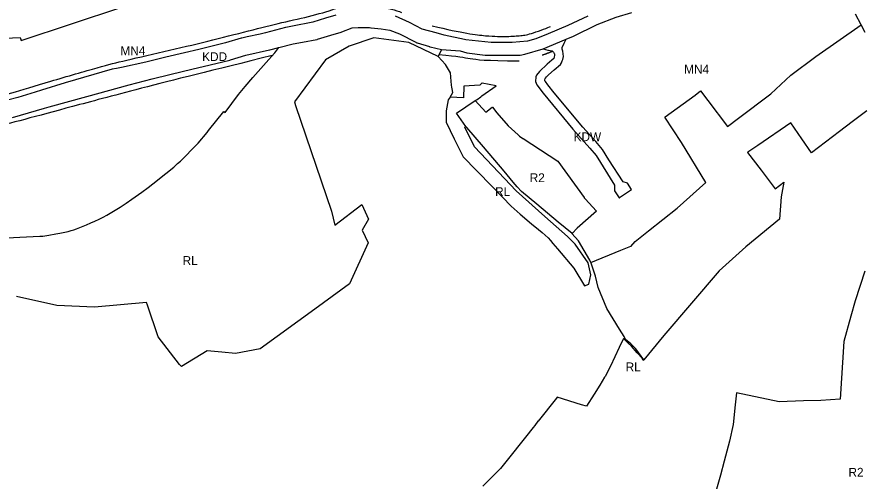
# Model space of a CAD drawing. Extents: x 7413438 to 7416393, y 5541665 to 5544118.
# Drawn here: x 7414051 to 7414626, y 5542093 to 5542408 of the extents above; entities that cross this region are included whole.
import ezdxf

# ---------------------------------------------------------------- set-up
doc = ezdxf.new("R2010")
doc.units = 0
for name, color, linetype in [('linie_rozgraniczajace', 7, 'Continuous'), ('linie_zabudowy_nieprzekraczalne', 7, 'Continuous'), ('oznaczenia_przeznaczen', 7, 'Continuous')]:
    doc.layers.add(name, color=color, linetype=linetype)

msp = doc.modelspace()

# ---------------------------------------------------------------- linework, layer by layer
at = {"layer": 'linie_rozgraniczajace'}
for p, q in [((7414054.25, 5542392.12), (7414122.55, 5542414.66)), ((7414458.25, 5542407.86), (7414468.88, 5542411.04)), ((7414260.97, 5542407.08), (7414252.35, 5542404.42)), ((7414261, 5542407.09), (7414260.97, 5542407.08)), ((7414267.9, 5542409.18), (7414261, 5542407.09)), ((7414317.89, 5542404.33), (7414308.55, 5542408.59)), ((7414438.96, 5542408.53), (7414425.48, 5542402.16)), ((7414445.44, 5542402.83), (7414458.25, 5542407.86)), ((7414624.64, 5542402.58), (7414620.71, 5542409.88)), ((7414233.79, 5542400.73), (7414220.22, 5542397.26)), ((7414233.97, 5542400.78), (7414233.78, 5542400.9)), ((7414233.78, 5542400.9), (7414233.79, 5542400.73)), ((7414238.46, 5542401.79), (7414233.97, 5542400.78)), ((7414252.35, 5542404.42), (7414238.46, 5542401.79)), ((7414271.96, 5542397.89), (7414279.06, 5542400.58)), ((7414279.06, 5542400.58), (7414283.2, 5542400.95)), ((7414283.2, 5542400.95), (7414290.85, 5542400.77)), ((7414290.85, 5542400.77), (7414291.73, 5542400.67)), ((7414291.73, 5542400.67), (7414291.88, 5542400.65)), ((7414291.88, 5542400.65), (7414292.03, 5542400.64)), ((7414292.03, 5542400.64), (7414298.76, 5542399.86)), ((7414298.76, 5542399.86), (7414298.76, 5542399.86)), ((7414298.76, 5542399.86), (7414304.5, 5542399.11)), ((7414304.5, 5542399.11), (7414311.09, 5542396.59)), ((7414326.66, 5542399.81), (7414317.89, 5542404.33)), ((7414336.03, 5542397.24), (7414326.66, 5542399.81)), ((7414425.48, 5542402.16), (7414412.19, 5542396.53)), ((7414429.21, 5542395.06), (7414445.44, 5542402.83)), ((7414593.86, 5542381.07), (7414624.64, 5542402.58)), ((7414627.37, 5542397.55), (7414624.64, 5542402.58)), ((7414012.45, 5542392.63), (7414053.52, 5542393.94)), ((7414053.52, 5542393.94), (7414054.25, 5542392.12)), ((7414203.61, 5542393.52), (7414193.03, 5542390.35)), ((7414203.92, 5542393.61), (7414203.61, 5542393.52)), ((7414204.02, 5542393.63), (7414203.92, 5542393.61)), ((7414207.72, 5542394.46), (7414204.02, 5542393.63)), ((7414216.45, 5542396.42), (7414207.72, 5542394.46)), ((7414220.22, 5542397.26), (7414216.45, 5542396.42)), ((7414255.57, 5542392.85), (7414264.49, 5542395.61)), ((7414264.49, 5542395.61), (7414271.58, 5542397.75)), ((7414271.58, 5542397.75), (7414271.62, 5542397.77)), ((7414271.62, 5542397.77), (7414271.96, 5542397.89)), ((7414293.72, 5542393.72), (7414276.97, 5542388.1)), ((7414317.51, 5542390.69), (7414293.72, 5542393.72)), ((7414311.09, 5542396.59), (7414322.2, 5542390.83)), ((7414341.54, 5542395.73), (7414336.03, 5542397.24)), ((7414355.19, 5542392.68), (7414341.54, 5542395.73)), ((7414403.71, 5542393.12), (7414398.17, 5542391.67)), ((7414412.19, 5542396.53), (7414403.71, 5542393.12)), ((7414424.38, 5542393), (7414429.21, 5542395.06)), ((7414193.03, 5542390.35), (7414174.99, 5542385.95)), ((7414229.25, 5542387.19), (7414238.99, 5542389.68)), ((7414238.99, 5542389.68), (7414245.35, 5542390.88)), ((7414245.35, 5542390.88), (7414254.92, 5542392.69)), ((7414254.92, 5542392.69), (7414255.21, 5542392.75)), ((7414255.21, 5542392.75), (7414255.57, 5542392.85)), ((7414276.97, 5542388.1), (7414260.96, 5542378.9)), ((7414337.37, 5542381.24), (7414317.51, 5542390.69)), ((7414322.2, 5542390.83), (7414322.53, 5542390.67)), ((7414322.53, 5542390.67), (7414322.89, 5542390.52)), ((7414322.89, 5542390.52), (7414323.19, 5542390.42)), ((7414323.19, 5542390.42), (7414331.54, 5542387.83)), ((7414331.54, 5542387.83), (7414331.62, 5542387.81)), ((7414331.62, 5542387.81), (7414331.94, 5542387.72)), ((7414331.94, 5542387.72), (7414339.68, 5542385.89)), ((7414356.1, 5542392.58), (7414355.19, 5542392.68)), ((7414373.36, 5542390.6), (7414356.1, 5542392.58)), ((7414387.66, 5542390.72), (7414373.36, 5542390.6)), ((7414398.17, 5542391.67), (7414387.66, 5542390.72)), ((7414408.81, 5542386.36), (7414424.38, 5542393)), ((7414421.51, 5542387.31), (7414423.08, 5542390.25)), ((7414423.08, 5542390.25), (7414424.38, 5542393)), ((7414165.25, 5542383.67), (7414152.52, 5542380.7)), ((7414174.99, 5542385.95), (7414165.25, 5542383.67)), ((7414196.33, 5542378.81), (7414206.85, 5542381.97)), ((7414206.85, 5542381.97), (7414222.93, 5542385.57)), ((7414222.49, 5542379.11), (7414226.46, 5542383.68)), ((7414222.93, 5542385.57), (7414223.03, 5542385.59)), ((7414223.03, 5542385.59), (7414223.11, 5542385.61)), ((7414223.11, 5542385.61), (7414229.25, 5542387.19)), ((7414226.46, 5542383.68), (7414229.25, 5542387.19)), ((7414339.68, 5542385.89), (7414337.37, 5542381.24)), ((7414339.68, 5542385.89), (7414352.4, 5542385.1)), ((7414352.4, 5542385.1), (7414356.84, 5542383.72)), ((7414356.84, 5542383.72), (7414369.4, 5542382.14)), ((7414369.4, 5542382.14), (7414393.13, 5542382)), ((7414393.13, 5542382), (7414396.19, 5542382.8)), ((7414396.19, 5542382.8), (7414408.81, 5542386.36)), ((7414408.81, 5542386.36), (7414411.92, 5542385.51)), ((7414411.92, 5542385.51), (7414412.29, 5542385.43)), ((7414412.29, 5542385.43), (7414414.92, 5542385.04)), ((7414414.92, 5542385.04), (7414415.82, 5542384.17)), ((7414415.82, 5542384.17), (7414416.26, 5542383.27)), ((7414416.41, 5542381.77), (7414416.17, 5542380.91)), ((7414416.26, 5542383.27), (7414416.31, 5542382.97)), ((7414416.31, 5542382.97), (7414416.41, 5542381.77)), ((7414421.58, 5542386.24), (7414421.51, 5542387.31)), ((7414422.15, 5542384.67), (7414421.58, 5542386.24)), ((7414422.48, 5542381.2), (7414422.15, 5542384.67)), ((7414139, 5542377.26), (7414122.31, 5542373.78)), ((7414152.41, 5542380.67), (7414139, 5542377.26)), ((7414152.48, 5542380.69), (7414152.41, 5542380.67)), ((7414152.52, 5542380.7), (7414152.48, 5542380.69)), ((7414177.8, 5542374.28), (7414196.03, 5542378.73)), ((7414196.03, 5542378.73), (7414196.33, 5542378.81)), ((7414211.64, 5542366.91), (7414222.49, 5542379.11)), ((7414260.96, 5542378.9), (7414239.79, 5542350.3)), ((7414342.42, 5542375.76), (7414337.37, 5542381.24)), ((7414411.48, 5542375.92), (7414406.23, 5542371.01)), ((7414414.65, 5542378.67), (7414411.48, 5542375.92)), ((7414415.87, 5542379.85), (7414414.65, 5542378.67)), ((7414416.17, 5542380.91), (7414415.87, 5542379.85)), ((7414420.37, 5542375.7), (7414421.16, 5542376.76)), ((7414421.16, 5542376.76), (7414421.67, 5542378.14)), ((7414421.67, 5542378.14), (7414422.01, 5542379.07)), ((7414422.01, 5542379.07), (7414422.48, 5542381.2)), ((7414576.88, 5542368.47), (7414593.86, 5542381.07)), ((7414116.07, 5542372.48), (7414084.17, 5542363.26)), ((7414119.07, 5542373.11), (7414116.07, 5542372.48)), ((7414122.31, 5542373.78), (7414119.07, 5542373.11)), ((7414155.31, 5542369.03), (7414171, 5542372.69)), ((7414171, 5542372.69), (7414177.75, 5542374.27)), ((7414177.75, 5542374.27), (7414177.79, 5542374.28)), ((7414177.79, 5542374.28), (7414177.8, 5542374.28)), ((7414345.68, 5542370.15), (7414342.42, 5542375.76)), ((7414345.95, 5542367.32), (7414345.68, 5542370.15)), ((7414406.23, 5542371.01), (7414404.17, 5542368.5)), ((7414412.23, 5542368.62), (7414416.22, 5542372.09)), ((7414416.22, 5542372.09), (7414420.37, 5542375.7)), ((7414127.52, 5542361.97), (7414143.16, 5542365.94)), ((7414143.16, 5542365.94), (7414155.31, 5542369.03)), ((7414206.46, 5542360.78), (7414211.64, 5542366.91)), ((7414345.96, 5542367.21), (7414345.95, 5542367.32)), ((7414346.49, 5542361.75), (7414345.96, 5542367.21)), ((7414403.76, 5542367.41), (7414403.56, 5542364.21)), ((7414404.17, 5542368.5), (7414403.76, 5542367.41)), ((7414409.79, 5542365.36), (7414409.96, 5542366.12)), ((7414409.92, 5542364.59), (7414409.79, 5542365.36)), ((7414410.21, 5542364.08), (7414409.92, 5542364.59)), ((7414409.96, 5542366.12), (7414410.21, 5542366.54)), ((7414410.21, 5542366.54), (7414410.92, 5542367.44)), ((7414410.92, 5542367.44), (7414412.23, 5542368.62)), ((7414563.19, 5542355.72), (7414576.87, 5542368.42)), ((7414576.87, 5542368.42), (7414576.88, 5542368.47)), ((7414084.17, 5542363.26), (7414067.98, 5542358.31)), ((7414098.93, 5542353.94), (7414127.52, 5542361.97)), ((7414201.87, 5542355.27), (7414206.46, 5542360.78)), ((7414346.78, 5542360.23), (7414346.49, 5542361.75)), ((7414346.99, 5542359.1), (7414346.78, 5542360.23)), ((7414347.45, 5542356.73), (7414346.99, 5542359.1)), ((7414354.75, 5542360.99), (7414354.55, 5542353.08)), ((7414365.79, 5542361.79), (7414354.75, 5542360.99)), ((7414367.01, 5542363.05), (7414365.79, 5542361.79)), ((7414367.2, 5542363.02), (7414367.01, 5542363.05)), ((7414367.12, 5542354.36), (7414376.73, 5542361.17)), ((7414376.73, 5542361.17), (7414367.2, 5542363.02)), ((7414403.56, 5542364.21), (7414404.3, 5542361.98)), ((7414404.3, 5542361.98), (7414408.79, 5542356.23)), ((7414411.81, 5542362.02), (7414410.21, 5542364.08)), ((7414416.13, 5542356.59), (7414411.81, 5542362.02)), ((7414051.95, 5542353.4), (7414045.09, 5542351.41)), ((7414063.69, 5542357), (7414051.95, 5542353.4)), ((7414067.98, 5542358.31), (7414063.69, 5542357)), ((7414073.25, 5542347.07), (7414098.86, 5542353.92)), ((7414098.86, 5542353.92), (7414098.93, 5542353.94)), ((7414192.88, 5542343.18), (7414201.87, 5542355.27)), ((7414345.46, 5542353.6), (7414344.28, 5542351.71)), ((7414345.48, 5542353.6), (7414345.46, 5542353.6)), ((7414345.48, 5542353.6), (7414347.45, 5542356.73)), ((7414354.55, 5542353.08), (7414345.48, 5542353.6)), ((7414363.86, 5542352.05), (7414366.45, 5542353.88)), ((7414366.45, 5542353.88), (7414367.12, 5542354.36)), ((7414408.79, 5542356.23), (7414428.75, 5542331.89)), ((7414435.58, 5542333.28), (7414416.13, 5542356.59)), ((7414491.64, 5542340.29), (7414511.99, 5542354.92)), ((7414511.99, 5542354.92), (7414515.61, 5542357.8)), ((7414515.61, 5542357.8), (7414520.5, 5542351.34)), ((7414541.28, 5542339.31), (7414563.19, 5542355.71)), ((7414563.19, 5542355.71), (7414563.19, 5542355.72)), ((7414239.79, 5542350.3), (7414240.61, 5542347.9)), ((7414240.61, 5542347.9), (7414264.96, 5542276.28)), ((7414344.28, 5542351.71), (7414342.83, 5542344.32)), ((7414349.85, 5542342.75), (7414362.65, 5542351.24)), ((7414362.65, 5542351.24), (7414363.86, 5542352.05)), ((7414362.65, 5542351.24), (7414369.76, 5542343.48)), ((7414520.5, 5542351.34), (7414533.83, 5542333.73)), ((7414048.31, 5542339.85), (7414070.22, 5542346.19)), ((7414070.22, 5542346.19), (7414073.25, 5542347.07)), ((7414181.43, 5542330.86), (7414191.78, 5542343.73)), ((7414191.78, 5542343.73), (7414192.88, 5542343.18)), ((7414342.83, 5542344.32), (7414342.89, 5542336.48)), ((7414356.26, 5542333.68), (7414349.85, 5542342.75)), ((7414369.76, 5542343.48), (7414374.15, 5542346.66)), ((7414374.15, 5542346.66), (7414374.33, 5542346.66)), ((7414374.33, 5542346.66), (7414377.17, 5542342.99)), ((7414377.17, 5542342.99), (7414385.01, 5542334)), ((7414628.38, 5542344.36), (7414618.52, 5542336.78)), ((7414342.89, 5542336.48), (7414348.32, 5542325.32)), ((7414491.31, 5542339.96), (7414491.64, 5542340.29)), ((7414502.68, 5542322.8), (7414491.31, 5542339.96)), ((7414533.83, 5542333.73), (7414541.28, 5542339.31)), ((7414576.81, 5542336.08), (7414554.45, 5542320.76)), ((7414584.25, 5542325.3), (7414576.81, 5542336.08)), ((7414618.52, 5542336.78), (7414610.01, 5542330.29)), ((7414180.49, 5542329.62), (7414181.43, 5542330.86)), ((7414355.54, 5542333.08), (7414356.26, 5542333.68)), ((7414362.1, 5542319.88), (7414355.54, 5542333.08)), ((7414356.27, 5542333.69), (7414356.26, 5542333.68)), ((7414356.97, 5542332.87), (7414356.27, 5542333.69)), ((7414368.29, 5542319.93), (7414356.97, 5542332.87)), ((7414385.01, 5542334), (7414391.71, 5542327.99)), ((7414428.75, 5542331.89), (7414440.41, 5542318.96)), ((7414444.51, 5542323.38), (7414435.58, 5542333.28)), ((7414610.01, 5542330.29), (7414591, 5542315.79)), ((7414174.34, 5542322.42), (7414180.49, 5542329.62)), ((7414348.32, 5542325.32), (7414354.32, 5542313)), ((7414391.71, 5542327.99), (7414392.24, 5542327.45)), ((7414392.24, 5542327.45), (7414392.67, 5542327.13)), ((7414392.67, 5542327.13), (7414394.97, 5542325.44)), ((7414394.97, 5542325.44), (7414395.2, 5542325.59)), ((7414395.2, 5542325.59), (7414418.58, 5542310.07)), ((7414591, 5542315.79), (7414584.25, 5542325.3)), ((7414163.79, 5542311.52), (7414172.41, 5542320.27)), ((7414172.41, 5542320.27), (7414174.34, 5542322.42)), ((7414382.54, 5542298.28), (7414362.1, 5542319.88)), ((7414382.16, 5542303.32), (7414368.29, 5542319.93)), ((7414440.41, 5542318.96), (7414444.72, 5542313.89)), ((7414448.98, 5542317.97), (7414444.51, 5542323.38)), ((7414519.27, 5542295.67), (7414502.68, 5542322.8)), ((7414554.45, 5542320.76), (7414547.69, 5542316.14)), ((7414354.32, 5542313), (7414363.4, 5542303.75)), ((7414444.72, 5542313.89), (7414457.06, 5542293.87)), ((7414453.31, 5542310.96), (7414448.98, 5542317.97)), ((7414547.69, 5542316.14), (7414547.52, 5542316.01)), ((7414547.52, 5542316.01), (7414556.66, 5542303.97)), ((7414157.88, 5542306.04), (7414160.49, 5542308.45)), ((7414160.49, 5542308.45), (7414162.38, 5542310.09)), ((7414162.38, 5542310.09), (7414163.79, 5542311.52)), ((7414418.58, 5542310.07), (7414418.64, 5542310.06)), ((7414418.64, 5542310.06), (7414436.53, 5542285.39)), ((7414462.94, 5542296), (7414453.31, 5542310.96)), ((7414143.76, 5542294.79), (7414152.56, 5542301.8)), ((7414152.56, 5542301.8), (7414157.88, 5542306.04)), ((7414363.4, 5542303.75), (7414374.35, 5542292.59)), ((7414388.44, 5542295.8), (7414382.16, 5542303.32)), ((7414556.66, 5542303.97), (7414566.26, 5542291.33)), ((7414390.33, 5542290.06), (7414382.54, 5542298.28)), ((7414388.41, 5542295.78), (7414388.44, 5542295.8)), ((7414391.09, 5542292.58), (7414388.41, 5542295.78)), ((7414465.89, 5542295.21), (7414462.94, 5542296)), ((7414499.72, 5542278.19), (7414519.27, 5542295.67)), ((7414566.26, 5542291.33), (7414572.07, 5542295.96)), ((7414572.07, 5542295.96), (7414570.32, 5542285.88)), ((7414136.09, 5542289.02), (7414140.39, 5542292.14)), ((7414140.39, 5542292.14), (7414143.76, 5542294.79)), ((7414374.35, 5542292.59), (7414381.14, 5542285.68)), ((7414409.94, 5542272.52), (7414390.33, 5542290.06)), ((7414393.94, 5542289.49), (7414391.09, 5542292.58)), ((7414457.06, 5542293.87), (7414457.2, 5542289.88)), ((7414457.2, 5542289.88), (7414460.38, 5542285.18)), ((7414460.59, 5542285.48), (7414468.58, 5542290.97)), ((7414468.58, 5542290.97), (7414465.89, 5542295.21)), ((7414125.52, 5542281.56), (7414129.33, 5542284.29)), ((7414129.33, 5542284.29), (7414136.09, 5542289.02)), ((7414381.14, 5542285.68), (7414387.09, 5542279.62)), ((7414404.48, 5542280.87), (7414393.94, 5542289.49)), ((7414436.53, 5542285.39), (7414436.52, 5542285.38)), ((7414436.52, 5542285.38), (7414436.61, 5542285.29)), ((7414436.61, 5542285.29), (7414437.19, 5542284.49)), ((7414437.19, 5542284.49), (7414437.28, 5542284.55)), ((7414437.28, 5542284.55), (7414444.98, 5542276.06)), ((7414460.38, 5542285.18), (7414460.49, 5542285.26)), ((7414460.49, 5542285.26), (7414460.59, 5542285.48)), ((7414570.32, 5542285.88), (7414569.26, 5542270.7)), ((7414112.41, 5542273.47), (7414121.45, 5542278.97)), ((7414121.45, 5542278.97), (7414125.52, 5542281.56)), ((7414267.35, 5542266.61), (7414285.58, 5542280.63)), ((7414285.58, 5542280.63), (7414290, 5542270.76)), ((7414387.09, 5542279.62), (7414393.15, 5542274.24)), ((7414418.96, 5542268.75), (7414404.48, 5542280.87)), ((7414480.16, 5542262.73), (7414499.72, 5542278.19)), ((7414110.02, 5542272.11), (7414112.41, 5542273.47)), ((7414264.96, 5542276.28), (7414267.35, 5542266.61)), ((7414393.15, 5542274.24), (7414400.88, 5542267.66)), ((7414425.25, 5542258.91), (7414409.94, 5542272.52)), ((7414444.98, 5542276.06), (7414431.71, 5542264.52)), ((7414096.41, 5542265.88), (7414098.53, 5542266.83)), ((7414098.53, 5542266.83), (7414101.68, 5542268.22)), ((7414101.68, 5542268.22), (7414104.33, 5542269.46)), ((7414104.33, 5542269.46), (7414107.13, 5542270.76)), ((7414107.13, 5542270.76), (7414107.14, 5542270.76)), ((7414107.14, 5542270.76), (7414110.02, 5542272.11)), ((7414290, 5542270.76), (7414285.72, 5542263.21)), ((7414400.88, 5542267.66), (7414405.51, 5542263.72)), ((7414419, 5542268.75), (7414418.96, 5542268.75)), ((7414428.29, 5542261.1), (7414419, 5542268.75)), ((7414569.26, 5542270.7), (7414546.4, 5542251.99)), ((7414077.88, 5542260.7), (7414080.63, 5542261.19)), ((7414080.63, 5542261.19), (7414083.96, 5542261.92)), ((7414083.96, 5542261.92), (7414086.08, 5542262.42)), ((7414086.08, 5542262.42), (7414088.31, 5542263.01)), ((7414088.31, 5542263.01), (7414090, 5542263.47)), ((7414090, 5542263.47), (7414091.75, 5542264.08)), ((7414091.75, 5542264.08), (7414096.41, 5542265.88)), ((7414285.72, 5542263.21), (7414289.79, 5542254.57)), ((7414405.51, 5542263.72), (7414407.94, 5542261.65)), ((7414407.94, 5542261.65), (7414412.03, 5542258.17)), ((7414428.27, 5542261.08), (7414428.29, 5542261.1)), ((7414432.8, 5542256.05), (7414428.27, 5542261.08)), ((7414431.71, 5542264.52), (7414428.29, 5542261.1)), ((7414471.15, 5542255.61), (7414480.16, 5542262.73)), ((7414044.42, 5542258.1), (7414057.78, 5542258.79)), ((7414057.78, 5542258.79), (7414067.05, 5542259.11)), ((7414067.05, 5542259.11), (7414069.03, 5542259.27)), ((7414069.03, 5542259.27), (7414073.03, 5542259.88)), ((7414073.03, 5542259.88), (7414077.88, 5542260.7)), ((7414412.03, 5542258.17), (7414413.69, 5542256.22)), ((7414413.69, 5542256.22), (7414415.37, 5542254.24)), ((7414430.38, 5542253.68), (7414425.25, 5542258.91)), ((7414440.34, 5542243.01), (7414432.8, 5542256.05)), ((7414468.25, 5542252.29), (7414471.15, 5542255.63)), ((7414471.15, 5542255.63), (7414471.15, 5542255.61)), ((7414289.79, 5542254.57), (7414277.24, 5542226.95)), ((7414415.37, 5542254.24), (7414418.54, 5542250.51)), ((7414418.54, 5542250.51), (7414429.63, 5542237.46)), ((7414439.22, 5542240.99), (7414430.38, 5542253.68)), ((7414441.07, 5542241.4), (7414461.53, 5542249.71)), ((7414461.53, 5542249.71), (7414468.19, 5542252.42)), ((7414468.19, 5542252.42), (7414468.25, 5542252.29)), ((7414546.4, 5542251.99), (7414528.25, 5542235.57)), ((7414441.16, 5542232.93), (7414439.22, 5542240.99)), ((7414441.07, 5542241.4), (7414440.34, 5542243.01)), ((7414441.31, 5542240.88), (7414441.07, 5542241.4)), ((7414444.27, 5542232.15), (7414441.31, 5542240.88)), ((7414429.63, 5542237.46), (7414436.75, 5542225.57)), ((7414439.79, 5542226.71), (7414441.16, 5542232.93)), ((7414528.25, 5542235.57), (7414490.62, 5542191.84)), ((7414627.04, 5542235.39), (7414620.54, 5542215.32)), ((7414277.24, 5542226.95), (7414253.63, 5542209.71)), ((7414436.75, 5542225.57), (7414439.79, 5542226.71)), ((7414445.99, 5542224.32), (7414444.27, 5542232.15)), ((7414452.01, 5542210.01), (7414445.99, 5542224.32)), ((7414078.37, 5542212.1), (7414051.03, 5542218.3)), ((7414620.54, 5542215.32), (7414617.62, 5542204.97)), ((7414104.04, 5542211.04), (7414078.37, 5542212.1)), ((7414139.46, 5542214.28), (7414104.04, 5542211.04)), ((7414140.1, 5542212.27), (7414139.46, 5542214.28)), ((7414147.26, 5542190.96), (7414140.1, 5542212.27)), ((7414253.63, 5542209.71), (7414216.65, 5542182.71)), ((7414460.59, 5542196.14), (7414452.01, 5542210.01)), ((7414617.62, 5542204.97), (7414612.79, 5542187.78)), ((7414463.68, 5542191.13), (7414460.59, 5542196.14)), ((7414161.83, 5542172.2), (7414147.26, 5542190.96)), ((7414463.15, 5542189.7), (7414460.31, 5542183.53)), ((7414466.53, 5542186.62), (7414463.15, 5542189.7)), ((7414464.68, 5542189.14), (7414463.68, 5542191.13)), ((7414468.23, 5542186.06), (7414464.68, 5542189.14)), ((7414468.8, 5542184.43), (7414466.53, 5542186.62)), ((7414490.62, 5542191.84), (7414477.17, 5542175.34)), ((7414612.79, 5542187.78), (7414610.31, 5542148.45)), ((7414180.47, 5542181.26), (7414163.23, 5542170.66)), ((7414190.54, 5542180.38), (7414180.47, 5542181.26)), ((7414216.65, 5542182.71), (7414199.76, 5542179.59)), ((7414460.31, 5542183.53), (7414454.51, 5542170.94)), ((7414471.55, 5542182.64), (7414468.23, 5542186.06)), ((7414472.63, 5542180.01), (7414468.8, 5542184.43)), ((7414477.17, 5542175.34), (7414471.55, 5542182.64)), ((7414199.76, 5542179.59), (7414190.54, 5542180.38)), ((7414475.96, 5542176.33), (7414472.63, 5542180.01)), ((7414476.71, 5542174.77), (7414475.96, 5542176.33)), ((7414477.17, 5542175.34), (7414476.71, 5542174.77)), ((7414163.23, 5542170.66), (7414161.83, 5542172.2)), ((7414454.51, 5542170.94), (7414450.8, 5542163.99)), ((7414450.44, 5542163.39), (7414447.28, 5542158.02)), ((7414450.64, 5542163.68), (7414450.44, 5542163.39)), ((7414450.8, 5542163.99), (7414450.64, 5542163.68)), ((7414447.28, 5542158.02), (7414443.3, 5542151.92)), ((7414443.3, 5542151.92), (7414438.03, 5542143.87)), ((7414539.94, 5542152.96), (7414539.06, 5542144.69)), ((7414568.85, 5542146.66), (7414539.94, 5542152.96)), ((7414417.75, 5542149.33), (7414405.23, 5542133.52)), ((7414418.25, 5542149.91), (7414417.75, 5542149.33)), ((7414434.84, 5542144.79), (7414418.25, 5542149.91)), ((7414585.5, 5542147.36), (7414568.85, 5542146.66)), ((7414597.33, 5542147.56), (7414585.5, 5542147.36)), ((7414610.31, 5542148.45), (7414597.33, 5542147.56)), ((7414438.03, 5542143.87), (7414434.84, 5542144.79)), ((7414539.06, 5542144.69), (7414537.64, 5542131.37)), ((7414401.89, 5542129.32), (7414396.64, 5542122.68)), ((7414402.99, 5542130.69), (7414401.88, 5542129.32)), ((7414401.88, 5542129.32), (7414401.89, 5542129.32)), ((7414405.19, 5542133.55), (7414402.99, 5542130.69)), ((7414405.23, 5542133.52), (7414405.19, 5542133.55)), ((7414537.64, 5542131.37), (7414535.17, 5542120.11)), ((7414396.64, 5542122.68), (7414392.3, 5542117.21)), ((7414535.17, 5542120.11), (7414531.67, 5542106.42)), ((7414387.85, 5542111.59), (7414382.54, 5542104.88)), ((7414388.73, 5542112.7), (7414387.85, 5542111.59)), ((7414392.3, 5542117.21), (7414388.73, 5542112.7)), ((7414531.67, 5542106.42), (7414529.01, 5542097.02)), ((7414379.8, 5542101.43), (7414376.55, 5542098.24)), ((7414382.54, 5542104.88), (7414379.8, 5542101.43)), ((7414376.55, 5542098.24), (7414372.56, 5542094.31)), ((7414529.01, 5542097.02), (7414523.67, 5542078.12)), ((7414372.56, 5542094.31), (7414367.68, 5542089.51))]:
    msp.add_line(p, q, dxfattribs=at)
at = {"layer": 'linie_zabudowy_nieprzekraczalne'}
for points, degree in [([(7413983.42, 5542391.67), (7413975.93, 5542383.31), (7413968.07, 5542372.87), (7413961.61, 5542367.64), (7413951.75, 5542357.6), (7413944.41, 5542351.85), (7413951.42, 5542351.96), (7413966.81, 5542351.37), (7413993.57, 5542348.41), (7413996.71, 5542346.81), (7414001.57, 5542347.51), (7414007.7, 5542347.53), (7414018.88, 5542349.04), (7414033.73, 5542352.7), (7414045.1, 5542355.56), (7414072.97, 5542364), (7414109.91, 5542374.85), (7414122.61, 5542377.91), (7414155.85, 5542385.56), (7414184.53, 5542392.37), (7414212.91, 5542399.7), (7414233.97, 5542404.86), (7414254.75, 5542409.33), (7414272.68, 5542415.25), (7414275.42, 5542416.19), (7414284.57, 5542416.89), (7414290.06, 5542416.76), (7414296.11, 5542415.63), (7414309.03, 5542412.62), (7414312.52, 5542411.12)], 3), ([(7414333.35, 5542402.05), (7414354.35, 5542396.92), (7414371.71, 5542394.77), (7414384.53, 5542394.66), (7414394.04, 5542395.28), (7414400.24, 5542396.32), (7414412.25, 5542400.88), (7414413.76, 5542401.52)], 3), ([(7414224.75, 5542381.75), (7414144.14, 5542362.04), (7414083.57, 5542345.67), (7414026.49, 5542330.32), (7414015.48, 5542328.23), (7414008.78, 5542327.55), (7414000.84, 5542327.51), (7413975.89, 5542330.4)], 3), ([(7414392.33, 5542377.97), (7414369.25, 5542378.11), (7414357.9, 5542379.51), (7414351.62, 5542381.1), (7414337.87, 5542382.32)], 3), ([(7414415.21, 5542384.67), (7414412.26, 5542383.47), (7414408.14, 5542382)], 2)]:
    msp.add_open_spline(points, degree=degree, dxfattribs=at)

# ---------------------------------------------------------------- texts
at = {"layer": 'oznaczenia_przeznaczen'}
for s, p in [('MN4', (7414121.65, 5542382.06)), ('KDD', (7414177.16, 5542378.04)), ('MN4', (7414504.44, 5542369.55)), ('KDW', (7414429.38, 5542323.66)), ('R2', (7414399.56, 5542295.86)), ('RL', (7414376.07, 5542286.4)), ('RL', (7414163.9, 5542239.66)), ('RL', (7414464.72, 5542167.48)), ('R2', (7414616.02, 5542095.91))]:
    msp.add_text(s, height=6, dxfattribs=at).set_placement(p)

doc.saveas('drawing.dxf')
